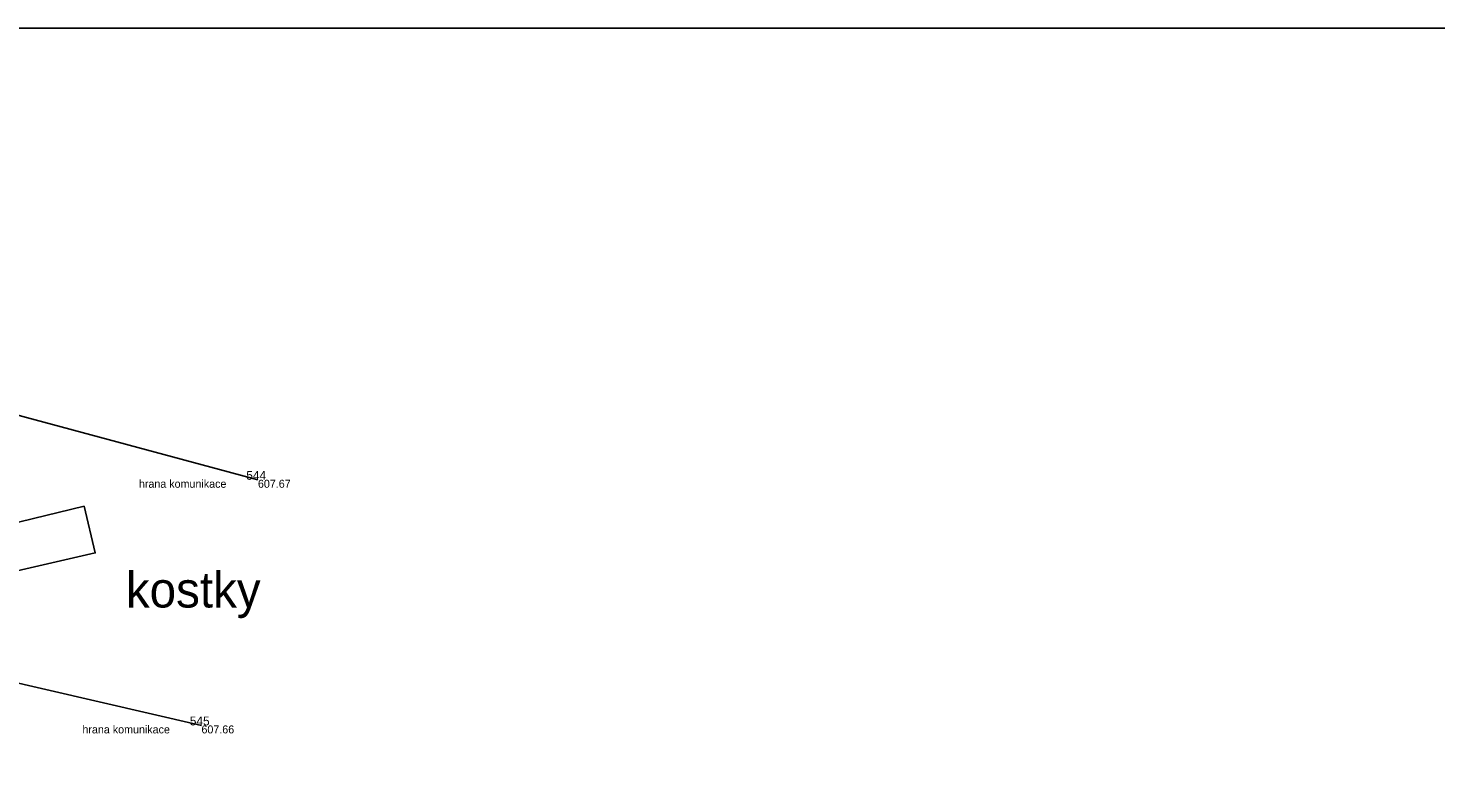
# Model space of a CAD drawing. Extents: x -866441 to -866144, y -1037389 to -1036968.
# Drawn here: x -866285.05 to -866269.23, y -1037186.82 to -1037178.61 of the extents above; entities that cross this region are included whole.
import ezdxf

# ---------------------------------------------------------------- set-up
doc = ezdxf.new("R2010")
doc.units = 0
for name, color, linetype in [('1 hrana zpevněné komunikace', 7, 'Continuous'), ('43 lampa', 7, 'Continuous'), ('Bod', 7, 'Continuous'), ('Bod_popis', 7, 'Continuous'), ('Bod_výška', 7, 'Continuous'), ('Bod_číslo', 7, 'Continuous'), ('Formát', 7, 'Continuous'), ('Texty', 7, 'Continuous')]:
    doc.layers.add(name, color=color, linetype=linetype)

msp = doc.modelspace()

# ---------------------------------------------------------------- linework, layer by layer
at = {"layer": '1 hrana zpevněné komunikace'}
for p, q in [((-866286.488, -1037182.607), (-866282.469, -1037183.687)), ((-866287.378, -1037185.464), (-866283.104, -1037186.45))]:
    msp.add_line(p, q, dxfattribs=at)
at = {"layer": '43 lampa'}
msp.add_lwpolyline([(-866285.873, -1037186.345), (-866285.798, -1037186.345), (-866285.673, -1037186.435), (-866285.623, -1037186.58), (-866285.673, -1037186.725), (-866285.798, -1037186.815), (-866285.953, -1037186.815), (-866286.078, -1037186.725), (-866286.128, -1037186.58), (-866286.078, -1037186.435), (-866285.953, -1037186.345), (-866285.873, -1037186.345), (-866285.873, -1037184.335), (-866284.423, -1037183.985), (-866284.298, -1037184.51), (-866285.273, -1037184.735), (-866285.398, -1037184.22)], dxfattribs=at)
at = {"layer": 'Bod'}
for p, q in [((-866282.469, -1037183.687), (-866282.469, -1037183.687)), ((-866283.104, -1037186.45), (-866283.104, -1037186.45))]:
    msp.add_line(p, q, dxfattribs=at)
at = {"layer": 'Formát'}
msp.add_line((-866143.782, -1037178.607), (-866440.782, -1037178.607), dxfattribs=at)

# ---------------------------------------------------------------- texts
at = {"layer": 'Bod_popis'}
for p in [(-866283.807, -1037183.777), (-866284.442, -1037186.54)]:
    msp.add_text('hrana komunikace', height=0.09, dxfattribs=at).set_placement(p)
at = {"layer": 'Bod_výška'}
for s, p in [('607.67', (-866282.469, -1037183.777)), ('607.66', (-866283.104, -1037186.54))]:
    msp.add_text(s, height=0.09, dxfattribs=at).set_placement(p)
at = {"layer": 'Bod_číslo'}
for s, p in [('544', (-866282.6, -1037183.687)), ('545', (-866283.235, -1037186.45))]:
    msp.add_text(s, height=0.1, dxfattribs=at).set_placement(p)
at = {"layer": 'Texty'}
msp.add_text('kostky', height=0.4, dxfattribs=at).set_placement((-866283.954, -1037185.124))

doc.saveas('drawing.dxf')
